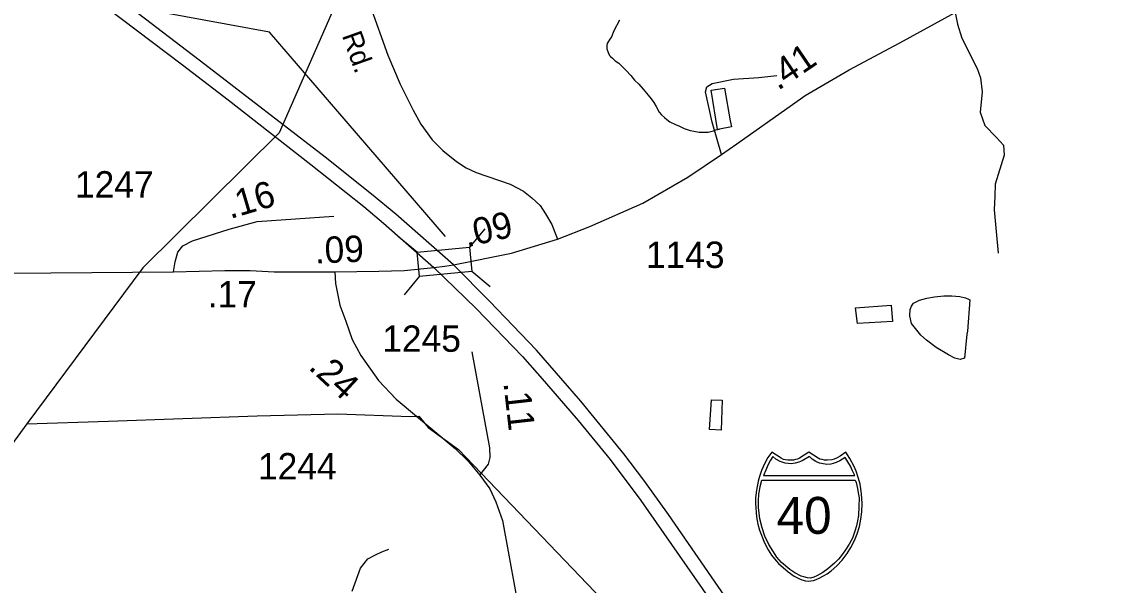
# Model space of a CAD drawing. Extents: x 2082433 to 2279600, y 546599 to 755198.
# Drawn here: x 2148963 to 2154071, y 587503 to 590172 of the extents above; entities that cross this region are included whole.
import ezdxf

# ---------------------------------------------------------------- set-up
doc = ezdxf.new("R2010")
doc.units = 0
for name, color, linetype in [('Exist Boundary Political Fire Districts', 7, 'Continuous'), ('Exist Hydrographic Misc Water Feature', 7, 'Continuous'), ('Exist Road Non-System Type 51', 7, 'Continuous'), ('Exist Road Primary Interstate Divided Center Attributed', 7, 'Continuous'), ('Exist Road Primary Interstate Shield CELL', 7, 'Continuous'), ('Exist Road Primary Interstate Shield Number Label', 7, 'Continuous'), ('Exist Road Secondary Mileage Hundredths English Label', 7, 'Continuous'), ('Exist Road Secondary Structure Standard Bridge CELL', 7, 'Continuous'), ('Exist Road Secondary Type 51 Attributed', 7, 'Continuous'), ('Exist Road Secondary Type 51 Label', 7, 'Continuous'), ('Exist Road Secondary Type 51 Number Label', 7, 'Continuous')]:
    doc.layers.add(name, color=color, linetype=linetype)

msp = doc.modelspace()

# ---------------------------------------------------------------- linework, layer by layer
at = {"layer": 'Exist Boundary Political Fire Districts'}
for points in [[(2151346, 601782.1), (2150536.8, 601359.3), (2150575.6, 601269.6), (2150804, 596727.4), (2150538.7, 590463.1), (2150181.1, 589645.7), (2149537.2, 589006.2), (2148987.7, 588267)], [(2148987.7, 588267), (2149374, 588280.6), (2150076.7, 588304.7), (2150459.7, 588315.4), (2150800.3, 588302.3), (2150842.6, 588304.3), (2150886.4, 588249.4), (2151029, 588145.6), (2153828.7, 585222.3), (2156045.8, 582536.1), (2162215, 581602.2)], [(2148987.7, 588267), (2148853.6, 588086.8), (2148166.4, 587162.7), (2149373.8, 581288.4), (2142989.3, 575675.9), (2139650, 576994.9)]]:
    msp.add_lwpolyline(points, dxfattribs=at)
at = {"layer": 'Exist Hydrographic Misc Water Feature'}
for points in [[(2151790.9, 590178.3), (2151765.1, 590128.3), (2151753.6, 590100), (2151745.2, 590088.3), (2151737.2, 590076.1), (2151733.3, 590068.2), (2151731.7, 590059.9), (2151731.7, 590052.2), (2151731.7, 590042.1), (2151735.6, 590030.1), (2151739.9, 590020.1), (2151745.8, 590010.3), (2151748.3, 590006.3)], [(2151748.3, 590006.3), (2151757.9, 589998.4), (2151770, 589986.4), (2151787.9, 589974.4), (2151800, 589962.4), (2151822.3, 589940.8), (2151844.2, 589916.8), (2151862.7, 589894.9), (2151882.8, 589874.9), (2151902.5, 589851.2), (2151926.9, 589823.2), (2151940.8, 589805.3), (2151952.9, 589789.2), (2151965, 589769.5), (2151979, 589743.5), (2151989.4, 589729.7), (2152003.6, 589717.9), (2152015.5, 589708), (2152029.6, 589697.8), (2152055.4, 589684.1), (2152075.7, 589676.2), (2152097.9, 589666.3), (2152125.6, 589656.4), (2152143.6, 589652.5), (2152167.6, 589648.9), (2152181.8, 589648.8), (2152193.7, 589648.6), (2152209.9, 589649), (2152223.8, 589650.9), (2152235.9, 589655.2), (2152247.6, 589659.1), (2152254.3, 589660.7), (2152264, 589663.1)], [(2152264, 589663.1), (2152254.3, 589660.7), (2152224.8, 589847), (2152288.6, 589857.3), (2152315.5, 589701.5)], [(2152315.5, 589701.5), (2152321.4, 589673.5), (2152264, 589663.1)], [(2153436.7, 588706), (2153434.8, 588692.1), (2153423.4, 588578.2), (2153403.3, 588571.9), (2153377, 588577.9), (2153347.5, 588593.8), (2153289, 588629.3), (2153242.9, 588663.1), (2153216.7, 588686.9), (2153190.6, 588718.8), (2153172.4, 588742.7), (2153164.4, 588778.3), (2153166, 588808.5), (2153172, 588824.6), (2153182, 588838.5), (2153209.9, 588852.6), (2153245.6, 588863), (2153281.5, 588869.3), (2153325.5, 588873.6), (2153363.9, 588873.5), (2153401.8, 588869.8), (2153427.7, 588863.9), (2153442, 588858.1), (2153447.8, 588854), (2153436.7, 588706)], [(2152908.1, 588817.1), (2153076, 588829.8), (2153082.6, 588752.2), (2152916.7, 588743.2), (2152908.1, 588817.1)], [(2152271.8, 588237.7), (2152217.4, 588241.4), (2152226.9, 588381.5), (2152276.7, 588379.7), (2152271.8, 588237.7)]]:
    msp.add_lwpolyline(points, dxfattribs=at)
at = {"layer": 'Exist Road Non-System Type 51'}
for points in [[(2153378.9, 590215.5), (2153390, 590160.1), (2153409.9, 590093.7), (2153483, 589949.7), (2153498.5, 589905.4), (2153507.4, 589838.9), (2153497.4, 589743.7), (2153519.6, 589679.4), (2153572.7, 589624), (2153608.2, 589586.4), (2153610.4, 589539.9), (2153568.3, 589402.5), (2153566.1, 589344.9), (2153563.9, 589280.7), (2153582.7, 589074.7)], [(2152273.6, 589542.1), (2152229.3, 589694.9), (2152198.3, 589838.9), (2152204.9, 589863.3), (2152229.3, 589878.8), (2152331.2, 589898.7), (2152450.8, 589907.6), (2152535, 589916.4)], [(2150526.2, 587475.6), (2150565.8, 587584.6), (2150601.5, 587628.1), (2150637.1, 587647.9), (2150666.9, 587661.8), (2150700.5, 587673.7)]]:
    msp.add_lwpolyline(points, dxfattribs=at)
at = {"layer": 'Exist Road Primary Interstate Divided Center Attributed'}
for points in [[(2151006.7, 589021), (2150733.3, 589260), (2150617.6, 589355.2), (2150398.8, 589530.4), (2149829.7, 589968.3), (2149262.2, 590404.1), (2149019.6, 590612.8), (2148903.9, 590726.4), (2148711.5, 590930.7), (2148609.9, 591061.6), (2148519.2, 591180.5), (2148331.1, 591442.2), (2148148.4, 591707.2), (2147853.5, 592128.8)], [(2147780.3, 592112.2), (2148038.2, 591749.3), (2148208.9, 591501.7), (2148497.5, 591090.8), (2148604.5, 590954.5), (2148687.8, 590854), (2148780.7, 590752.3), (2148832.6, 590699.3), (2148999.2, 590530), (2149221.2, 590349), (2149724.8, 589967.2), (2149939.8, 589801.4), (2150330.7, 589495.8), (2150582, 589295.7), (2150674.9, 589217.8), (2150912.7, 589007)], [(2155629, 582587.9), (2155435.5, 582856.1), (2155292.3, 583068.1), (2155114, 583327.6), (2154841.6, 583725.6), (2154240.1, 584601.5), (2153826.1, 585206), (2153464.1, 585738), (2153212.8, 586100.2), (2152831.2, 586659.3), (2152584.8, 587019.4), (2152289.2, 587450.9), (2152023.3, 587838), (2151906.5, 588000.2), (2151812.5, 588125.7), (2151608.2, 588375.5), (2151398, 588616.6), (2151176.4, 588848), (2151006.7, 589021)], [(2150912.7, 589007), (2151113.7, 588813.4), (2151333.2, 588586.3), (2151436.9, 588468.5), (2151596.3, 588283.5), (2151746.6, 588098.6), (2151891.4, 587905.1), (2152182.2, 587488.7), (2152481, 587052.9), (2152771.8, 586626.9), (2153153.3, 586073.2), (2153740.7, 585210.3), (2154148.2, 584616.6), (2154758.4, 583726.6), (2155163.7, 583136.2), (2155389, 582806.4), (2155530.6, 582599.8)]]:
    msp.add_lwpolyline(points, dxfattribs=at)
at = {"layer": 'Exist Road Primary Interstate Shield CELL'}
for points in [[(2152687.1, 587522.8), (2152696.6, 587523.8), (2152709.3, 587526.2), (2152721.7, 587530.3), (2152735.8, 587536.5), (2152756.6, 587548.1), (2152773.4, 587557.9), (2152792.7, 587570.9), (2152818.8, 587594.6), (2152844.9, 587622), (2152867.9, 587653.1), (2152886.1, 587682.1), (2152902.2, 587715.2), (2152915.6, 587746.1), (2152926.3, 587781.5), (2152933.4, 587815.7), (2152936.9, 587851.4), (2152939.3, 587891), (2152936.6, 587935.5), (2152928.9, 587981.1), (2152921.6, 588009.4), (2152910.6, 588043.4), (2152901.6, 588065), (2152880.8, 588103.5), (2152862, 588133.1), (2152834.8, 588113.9), (2152817, 588104.5), (2152806.2, 588099.6), (2152795, 588097.4), (2152774.5, 588094.9), (2152761.6, 588095.5), (2152749.7, 588098.2), (2152739.6, 588100.4), (2152731.3, 588104.5), (2152687.1, 588133.1), (2152642.8, 588104.5), (2152633.5, 588100.2), (2152624, 588098.2), (2152614.9, 588095.7), (2152599.7, 588094.9), (2152588.2, 588095.3), (2152576.3, 588097.4), (2152566.9, 588099.4), (2152556.4, 588104.5), (2152511.3, 588133.1), (2152493.6, 588107.4), (2152479.1, 588082), (2152463.7, 588046), (2152454.2, 588018.2), (2152447.4, 587995.3), (2152439, 587953.4), (2152434.7, 587916.8), (2152434, 587891), (2152438.7, 587826.5), (2152445.8, 587792.1), (2152453, 587764.3), (2152476.9, 587704.3), (2152494.8, 587670.7), (2152510.2, 587646.5), (2152531.8, 587619.3), (2152543.5, 587606.4), (2152588.3, 587567.2), (2152618.2, 587546.8), (2152642.1, 587533.9), (2152653.3, 587529.6), (2152670.9, 587524.7)], [(2152516.7, 588112.3), (2152505.7, 588095.4), (2152493, 588072.6), (2152482.9, 588048.9), (2152472.5, 588022.7), (2152904.1, 588022.6), (2152894, 588045), (2152883.2, 588067.5), (2152872, 588088.1), (2152858.3, 588108), (2152834.1, 588092.8), (2152816.5, 588084.4), (2152802.3, 588079.5), (2152790.3, 588076.8), (2152771.7, 588075.4), (2152763.4, 588075.9), (2152737.4, 588081.7), (2152719.9, 588088.9), (2152703.2, 588100), (2152689.7, 588112.8), (2152655.5, 588092.1), (2152640.3, 588085.4), (2152622.9, 588080.9), (2152603.8, 588078.6), (2152574.3, 588081.7), (2152551.3, 588089.7), (2152531.4, 588100)], [(2152906.6, 588001.3), (2152911.2, 587989.1), (2152917.6, 587962.1), (2152920.9, 587941.2), (2152924.3, 587917.2), (2152923.2, 587876.1), (2152921.2, 587833.5), (2152917.3, 587808.3), (2152912, 587785.4), (2152904.9, 587759.9), (2152893.3, 587726.1), (2152877.4, 587697.4), (2152857.5, 587665.6), (2152836.1, 587637.7), (2152826.7, 587626.2), (2152809, 587607.5), (2152776.8, 587581.6), (2152753.3, 587564), (2152725.1, 587547.4), (2152710.8, 587541), (2152694.1, 587537.5), (2152680.4, 587538.5), (2152663.8, 587542.9), (2152650.4, 587546.6), (2152620.9, 587562.5), (2152597.1, 587578.4), (2152557.3, 587611.1), (2152535.9, 587636.2), (2152515.8, 587665.6), (2152497.9, 587695.7), (2152478.9, 587735.3), (2152465.4, 587775.2), (2152455.6, 587818.3), (2152449, 587871), (2152448.3, 587903), (2152450.2, 587933.9), (2152453.2, 587950), (2152457.1, 587970.1), (2152465, 588001.1)]]:
    msp.add_lwpolyline(points, close=True, dxfattribs=at)
at = {"layer": 'Exist Road Secondary Mileage Hundredths English Label'}
msp.add_lwpolyline([(2150968.1, 589154.1), (2150136.2, 590121.2), (2147931.7, 590526.7)], dxfattribs=at)
at = {"layer": 'Exist Road Secondary Structure Standard Bridge CELL'}
for p, q in [((2151153.8, 589191.1), (2151081.6, 589104)), ((2150835, 589078.8), (2150747.8, 589151)), ((2150845.5, 588966.1), (2150773.3, 588878.9)), ((2151179.5, 588916.5), (2151092.4, 588988.7))]:
    msp.add_line(p, q, dxfattribs=at)
msp.add_lwpolyline([(2151092.4, 588988.7), (2150845.6, 588965.5), (2150834.8, 589080.8), (2151081.6, 589104)], close=True, dxfattribs=at)
at = {"layer": 'Exist Road Secondary Type 51 Attributed'}
for points in [[(2150611.4, 590246.3), (2150696.2, 590012.9), (2150753.2, 589875.1), (2150815.1, 589752.6), (2150851.3, 589686.4), (2150904.6, 589612.5), (2150955.4, 589561.7), (2151020.2, 589508.7), (2151065.6, 589479.5), (2151113.2, 589457.9), (2151274.8, 589401.7), (2151337.5, 589368.2), (2151376.4, 589336.8), (2151415.3, 589301.1), (2151441.2, 589262.2), (2151471.5, 589211.4), (2151498.5, 589142.1)], [(2151498.5, 589142.1), (2151651.1, 589201), (2151901.4, 589311.7), (2152114.1, 589435.8), (2152273.6, 589542.1), (2152346.7, 589593), (2152610.3, 589779.1), (2152670.1, 589821.2), (2152878.3, 589943), (2153117.5, 590071.5), (2153378.9, 590215.5)], [(2149682.3, 588987), (2149690.1, 589034.7), (2149701.7, 589079.9), (2149726.2, 589109.6), (2149771.4, 589134.1), (2149945.7, 589188.3), (2150078, 589225.8), (2150439.4, 589250.3)], [(2151006.7, 589021), (2151280.2, 589075.1), (2151498.5, 589142.1)], [(2150912.7, 589007), (2150965.7, 589014.5), (2151006.7, 589021)], [(2146207.7, 587933.5), (2146268.3, 588801.1), (2146285.5, 588846.1), (2146300.3, 588882.9), (2146346.9, 588919.7), (2146389, 588936.7), (2146421.1, 588940.1), (2146463.2, 588945.2), (2146515.3, 588948.2), (2146579.3, 588950.9), (2147103.2, 588964.3), (2148103, 588966.4), (2148326.3, 588976.2), (2149682.3, 588987)], [(2149682.3, 588987), (2149923.9, 588992.7), (2150044.3, 588992.7), (2150157.7, 588986.4), (2150445.2, 588987.5)], [(2150445.2, 588987.5), (2150653.3, 588990.8), (2150773.3, 588994), (2150912.7, 589007)], [(2150445.2, 588987.5), (2150448.5, 588932.4), (2150469, 588829.6), (2150496, 588753.9), (2150526.3, 588666.3), (2150567.4, 588591.7), (2150651.1, 588472.8), (2150735.4, 588384.1), (2151013.8, 588150.5), (2151075.4, 588091), (2151130.5, 588025.1)], [(2151130.5, 588025.1), (2151171.6, 588075.9), (2151179.1, 588108.3), (2151178, 588153.8), (2151094.3, 588609)], [(2151130.5, 588025.1), (2151177.5, 587959.1), (2151205.6, 587897.5), (2151238, 587809.9), (2151298, 587482.2), (2151364, 587114.6), (2151391, 586961), (2151426.6, 586830.2), (2151452.6, 586750.1), (2151523.9, 586590.1), (2151624.4, 586381.4), (2151798.5, 586014.8), (2151995, 585621), (2152223.8, 585108.6), (2152442.1, 584623.1)]]:
    msp.add_lwpolyline(points, dxfattribs=at)

# ---------------------------------------------------------------- texts
at = {"layer": 'Exist Road Primary Interstate Shield Number Label'}
msp.add_text('40', height=175, dxfattribs=at).set_placement((2152534.2, 587746.6))
at = {"layer": 'Exist Road Secondary Mileage Hundredths English Label'}
for s, rotation, p in [('.41', 34.2326, (2152541.4, 589843)), ('.16', 16.5349, (2149949.8, 589236.7)), ('.09', 13.1195, (2151068.2, 589102.3)), ('.09', 2.3197, (2150352.4, 589026.1)), ('.24', 317.1708, (2150315.7, 588530.6)), ('.11', 276.5115, (2151241.9, 588461))]:
    msp.add_text(s, height=125, rotation=rotation, dxfattribs=at).set_placement(p)
msp.add_text('.17', height=125, dxfattribs=at).set_placement((2149843.5, 588818.5))
at = {"layer": 'Exist Road Secondary Type 51 Label'}
msp.add_text('Rd.', height=95, rotation=289.6245, dxfattribs=at).set_placement((2150477.4, 590106))
at = {"layer": 'Exist Road Secondary Type 51 Number Label'}
for s, p in [('1247', (2149215.7, 589338.6)), ('1143', (2151916.2, 589005.4)), ('1245', (2150669.1, 588608.5)), ('1244', (2150081.4, 588004.1))]:
    msp.add_text(s, height=125, dxfattribs=at).set_placement(p)

doc.saveas('drawing.dxf')
